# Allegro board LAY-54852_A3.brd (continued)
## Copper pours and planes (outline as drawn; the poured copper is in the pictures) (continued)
LPD4X_VDDQ_0V6 on TOP: 68.64,42.84 69.79,42.84 70.11,42.51 70.11,36.3 69.76,35.95 68.38,35.95 68.38,38.37 68.04,38.71 68.04,41.11 68.55,41.63 68.55,42.76
NVCC_SD2 on L3_PWR: 90.3,50.98 90.48,50.98 90.72,50.74 91.91,50.74 92.31,50.34 92.31,38.89 86.16,32.73 72.27,32.73 67.67,37.34 60.42,37.34 59.97,37.79 59.97,39.35 60.11,39.5 72.18,39.5 73.12,38.55 73.12,35.73 73.79,35.07 84.5,35.07 90.83,41.4 90.83,49.69 90.24,50.27 90.24,50.92
PD_USB_VBUS_IN on TOP: 46.66,24.37 46.96,24.37 46.97,24.38 47.06,24.29 47.06,21.86 46.28,21.07 45.42,21.07 45.25,21.24 45.25,24.6 45.41,24.76 46.27,24.76
USB1_VBUS_IN on TOP: 23.62,19.36 25,19.36 25.59,18.77 25.59,16.48 25.61,16.47 25.53,16.39 25.06,16.39 24.64,15.98 24.64,15.38 23.58,14.31 23.19,14.31 23.1,14.23 23.1,13.59 23.38,13.31 23.89,13.31 24.11,13.08 24.11,12.62 23.92,12.43 22.03,12.43 21.53,12.93 21.53,14.52 22.09,15.09 23.16,15.09 23.46,15.38 23.46,19.2
USB_PD_VBUS_F on TOP: 38.48,13.67 40.33,13.67 40.48,13.52 40.48,8.86 39.76,8.14 36.12,8.14 35.48,8.78 35.48,11.79 36.33,12.64 37.45,12.64
USB_PD_VBUS_F on TOP: 47.65,24.98 47.65,23.14 47.54,23.04 47.4,23.04 47.28,23.16 47.28,24.31 47.03,24.56 46.86,24.56 46.62,24.8 46.62,26.77 46.76,26.9 48.27,26.9 48.67,26.51 48.67,25.6 48.38,25.31 47.98,25.31
USB_PD_VBUS_F on L3_PWR: 45.79,26.46 47.32,26.46 47.71,26.07 47.71,12.66 46.41,11.36 36.93,11.36 36.69,11.6 36.69,14.18 36.88,14.37 43.08,14.37 45.2,16.49 45.2,25.87
USBC_VBUS on TOP: 25.39,10.72 26.69,10.72 26.96,10.45 26.96,9.07 28.4,7.63 28.4,6.49 28.53,6.35 28.53,5.83 28.4,5.7 27.97,5.7 27.88,5.79 27.88,6.43 27.98,6.53 27.98,7.47 27.55,7.91 26.22,7.91 25.36,8.77 25.36,10.68
USBC_VBUS_F on TOP: 22.02,11.94 23.9,11.94 24.12,11.72 24.12,8.7 23.86,8.44 22.07,8.44 21.74,8.77 21.74,11.66
USBC_VBUS_F on TOP: 25.28,22.45 27.97,22.45 28.16,22.26 28.16,20.33 26.4,18.56 26.4,16.89 26.57,16.72 27.14,16.72 27.23,16.63 27.23,16.52 27.14,16.44 25.85,16.44 25.78,16.5 25.78,19.01 25.06,19.73 25.06,22.24
USBC_VBUS_F on BOTTOM: 23.37,20.05 27.07,20.05 27.56,19.55 27.56,17.82 27.09,17.36 24.77,17.36 24.26,16.84 24.26,11.04 23.84,10.62 22.23,10.62 21.52,11.34 21.52,18.2
VCAN_5V on TOP: 40.08,81.4 42.61,81.4 43.04,80.97 43.04,77.88 43.42,77.49 43.42,77.06 43.18,76.83 40.14,76.83 39.61,77.36 39.61,80.92
VMIC_1V8 on TOP: 13.25,77.41 15.53,77.41 16.14,76.8 16.14,76.03 15.3,75.19 15.3,73.62 14.98,73.3 14.07,73.3 12.89,74.48 12.89,76.62 13.09,76.82 13.09,77.25
VPCIE_3V3 on TOP: 113.88,14.99 115.6,14.99 115.75,14.84 115.75,10.09 114.92,9.26 113.37,9.26 112.44,8.32 112.44,7.84 112.24,7.64 109.91,7.64 109.61,7.94 109.61,11.23 110.44,12.06 112.49,12.06 113.3,12.87 113.3,14.41
VPCIE_3V3 on TOP: 132.4,14.88 136.07,14.88 136.53,14.43 136.53,12.38 136.85,12.06 136.85,9.55 137,9.39 133.31,9.39 132.4,10.3
VPCIE_3V3 on TOP: 132.26,36.46 133.38,36.46 133.7,36.78 135.86,36.78 135.97,36.88 137.24,36.88 137.41,36.7 137.41,35.61 136.93,35.13 135.91,35.13 135.74,35.3 133.11,35.3 132.7,34.89 132.7,33.79 132.67,33.77 132.4,33.77 132.33,33.83 132.33,35.21 132,35.55 132,36.2
VPCIE_3V3 on BOTTOM: 128.96,36.47 134.05,36.47 134.26,36.67 135.75,36.67 136.14,36.28 136.14,35.46 135.59,34.9 132.94,34.9 132.64,34.6 132.64,32.21 130.91,30.48 130.91,25.43 131.83,24.51 132.18,24.51 134.8,21.9 136.02,20.67 136.02,13.12 135.59,12.69 118.25,12.69 113.1,7.54 109.58,7.54 108.87,8.24 108.87,13.7 111.79,16.62 119.43,16.62 121.57,18.76 128.95,18.76 129.55,19.37 129.55,20.68 128.09,22.15 128.09,35.6
VRPI_3V3 on TOP: 86.68,78.79 87.63,78.79 89.08,77.34 89.08,74.71 88.79,74.41 87.54,74.41 87.3,74.65 84.75,74.65 84.2,75.2 84.2,77.09 84.38,77.27 85.75,77.27 86.17,77.69 86.17,78.29
VRPI_5V on TOP: 84.54,83.37 91.32,83.37 91.46,83.24 91.46,79.52 91.26,79.32 86.45,79.32 85.95,79.83 85.95,81.08 85.27,81.77 84.33,81.77 84.2,81.89 84.2,83.03
VSYS_5V on TOP: 69.88,30.45 69.88,29.56 69.74,29.42 68.03,29.42 68,29.46 68,30.39 68.12,30.51 69.82,30.51
VSYS_5V on TOP: 65.21,35.33 66.1,35.33 66.24,35.19 66.24,33.48 66.2,33.44 65.27,33.44 65.15,33.57 65.15,35.27
VSYS_5V on TOP: 36.37,45.09 42.79,45.09 45.56,42.32 48.87,42.32 49.3,41.89 51.15,41.89 51.32,41.72 51.32,41.12 52.35,41.12 52.53,40.93 52.58,40.97 53.94,40.97 54.55,41.58 54.55,42.87 55.22,43.54 58.49,43.54 59.28,42.74 59.28,41.05 58.51,40.27 57.61,40.27 57.04,39.7 57.04,38.16 56.74,37.85 53.91,37.85 53.18,38.57 49.08,38.57 47.79,39.87 44.22,39.87 42.59,41.5 38.71,41.5 36.98,43.23 36.28,43.23 35.99,43.52 35.99,44.71
VSYS_5V on TOP: 132.38,33.47 132.63,33.47 132.76,33.34 132.76,31.81 132.91,31.65 136.73,31.65 136.98,31.4 136.98,28.9 136.7,28.61 134.91,28.61 134.65,28.87 134.65,29.84 134.16,30.34 133.21,30.34 132.35,31.2 132.35,33.44
VSYS_5V on TOP: 28.68,22.23 32.89,22.23 33.06,22.07 33.06,21.44 32.25,20.64 32.25,20.13 32.05,19.93 29.85,19.93 28.35,18.43 27.39,18.43 27.18,18.22 27.18,16.89 27.11,16.81 26.71,16.81 26.5,17.02 26.5,18.39 28.44,20.33 28.44,21.99
VSYS_5V on TOP: 63.79,25.86 62.9,25.86 62.76,26 62.76,27.71 62.8,27.74 63.73,27.74 63.85,27.62 63.85,25.92
VSYS_5V on BOTTOM: 136.9,27.24 135.4,27.24 135.08,27.56 135.08,31.06 135.2,31.19 137.19,31.19 137.57,30.81 137.57,27.91
VSYS_5V on BOTTOM: 63.52,35.55 69.88,35.55 70.36,35.07 70.36,27.39 70.42,27.32 70.42,25.75 69.33,24.66 68.81,24.66 68.74,24.58 61.75,24.58 60.8,25.53 60.8,26.73 60.98,26.91 61.88,26.91 62.11,27.14 62.11,27.66 62.16,27.72 64.44,27.72 64.55,27.61 64.55,27.09 64.54,27.07 64.54,26.75 65.25,26.03 66.14,26.03 68.05,27.94 68.05,33.23 67.74,33.54 58.14,33.54 56.38,35.31 56.38,41.2 56.57,41.39 58.35,41.39 58.52,41.22 58.52,38.8 58.96,38.37 60.7,38.37
VSYS_5V on BOTTOM: 107.01,4 109.83,4 110.11,3.72 110.11,1.87 109.96,1.72 107.22,1.72 106.84,2.1 106.84,3.84
VSYS_5V on BOTTOM: 39.5,43.63 39.5,40.72 36.65,37.87 33.84,37.87 30.91,34.95 30.91,25.75 32.55,24.11 32.55,20.35 32.01,19.82 29.43,19.82 27.3,21.95 27.3,36.73 32.85,42.28 32.85,43.75 33.45,44.36 38.78,44.36
VSYS_5V on L3_PWR: 29.92,22.11 32.2,22.11 32.48,21.84 32.48,20.33 32.45,20.31 32.45,16.08 33,15.53 35.89,15.53 36.32,15.1 36.32,11.51 36.93,10.91 48.26,10.91 50.15,9.02 109.58,9.02 111.56,7.04 111.56,2.37 110.76,1.57 106.81,1.57 106.2,0.96 49.72,0.96 49.52,1.16 49.52,4.71 48.51,5.71 38.78,5.71 36.16,8.34 32.91,8.34 32.05,9.2 32.05,12.46 29.54,14.97 29.54,21.74 ; 1 cut-out
N111686466 on TOP: 35.71,42.16 36.78,42.16 38.89,40.05 42.95,40.05 43.52,39.49 43.52,37.85 42.87,37.2 41.2,37.2 39.72,35.72 39.72,34.32 39.56,34.16 39.41,34.16 39.3,34.26 39.3,34.96 39.32,34.97 39.32,37.01 36.97,39.35 36.97,41.13 36.51,41.59 35.59,41.59 35.46,41.73 35.46,41.9
N111686641 on TOP: 49.06,8.53 59.07,8.53 59.82,7.78 59.82,6.63 59.52,6.33 57.02,6.33 56.07,7.28 49.05,7.28 48.84,7.49 48.84,8.31
N113526638 on TOP: 66.33,38.02 67.6,38.02 67.66,37.96 67.66,35.72 67.01,35.08 67.01,33.52 66.93,33.43 66.48,33.43 66.34,33.57 66.34,38.01
N113526990 on TOP: 70.23,33.28 71.54,33.28 71.69,33.12 71.69,30.86 71.49,30.66 68.04,30.66 67.99,30.71 67.99,31.13 68.15,31.29 69.45,31.29 70.11,31.95 70.11,33.16
N113527183 on TOP: 72.3,29.69 73.83,29.69 74.41,29.11 75.47,29.11 75.61,28.97 75.61,25.21 75.53,25.14 73.83,25.14 72.76,26.2 72.26,26.2 72.22,26.25 72.22,29.61
N113527270 on TOP: 68.08,29.29 69.79,29.29 70.2,29.7 71.5,29.7 71.65,29.55 71.65,27.54 71.43,27.33 70.4,27.33 70.22,27.51 70.22,28.13 69.73,28.62 68.08,28.62 67.99,28.71 67.99,29.2
N113527504 on TOP: 64.57,27.68 64.65,27.6 64.65,25.37 64.75,25.27 64.75,22.88 64.63,22.76 63.54,22.76 63.39,22.91 63.39,25.18 63.96,25.76 63.96,27.56 64.08,27.68
N113527663 on TOP: 62.62,27.57 62.65,27.54 62.65,23.21 62.44,22.99 61.55,22.99 61.44,23.1 61.44,25.22 62.17,25.96 62.17,27.48 62.26,27.57
N113527832 on TOP: 64.19,37.97 65.07,37.97 65.21,37.83 65.21,35.77 65.02,35.58 65.02,33.54 64.98,33.5 64.45,33.5 64.39,33.56 64.39,35.84 64.1,36.14 64.1,37.88
N115751791 on TOP: 132.96,34.75 134.85,34.75 134.94,34.65 134.94,34.08 133.5,34.08 133.3,33.88 133.3,31.98 133.15,31.84 132.98,31.84 132.89,31.93 132.89,34.67
N115751791 on BOTTOM: 133.22,34.65 135.89,34.65 136.37,34.16 136.37,32.97 135.99,32.59 133.45,32.59 133.05,32.99 133.05,34.47
N115938225 on BOTTOM: 105.81,26.81 107.22,26.81 107.45,26.57 107.45,26.14 107.68,25.91 108.62,25.91 109.01,25.53 109.01,24.67 108.71,24.37 107.28,24.37 107.1,24.55 105.04,24.55 104.89,24.7 104.89,25.6 105.18,25.89 105.18,26.18
N115938505 on BOTTOM: 102.01,30.55 106.29,30.55 106.78,30.06 106.78,28.81 106,28.02 104.52,28.02 104.28,28.26 103.36,28.26 102.86,27.77 102.86,24.1 102.12,23.36 98,23.36 97.41,23.95 97.41,25.95

Small or netless copper shapes (teardrops, artwork), in the pictures only: 2 on TOP

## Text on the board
BOTTOM: 170-54852 REV A3
Ref Des/Silkscreen Bottom: 700-54852 REV X | SCH-54852 REV X | S/N
User.Comments: 22. THIS FAB_VIAFILL.ART SHOWS LOCATIONS OF VIA-IN-PAD TO BE FILLED.
Ref Des/Silkscreen Top: SW601[1:4] | 1100 | 0100 | FLEXSPI | 1011 | 0011 | MICROSD | EMMC | 1010 | 0010 | 1001 | DOWNLOAD | 0001 | CORTEX-M | CORTEX-A | GND | 5V | H | L | T0/1 | 1V8 | 3V3 | SCL | SDA | STBY | WDOG | FSUS | PWR | RC | FSL | LC | A | U | 1 | 17 | ON/OFF | RST | BMODE | CAN | PD | ADC | TAMPER | LPDDR4 | I2C CN | SW | M.2 | E | MicroSD | EXP CN | DBG | USB | ENET | AUD | IMU | MCIMX93-QSB A3
DIMENSION: GRID ORIGIN | PRIMARY DATUM | CANNOT ADD ANY PLANE ON EVERY LAYER ON THIS BOARD | 23.  ANTENNA BOARD CANNOT BE SEPERATED WITH THE MAIN BOARD.USE V-CUT FOR THE CONNECTION. | V-CUT DETAILS:   SEE DETAIL 'E' | CORE | 3.49 | 3.97 | 0.02 | THIS BOARD WAS DESIGNED FOR MAXIMUM FLEXIBILITY IN SOFTWARE DEVELOPMENT AND DEMONSTRATES | PRELIMINARY -SUBJECT TO CHANGE | NXP CONFIDENTIAL AND PROPRIETARY | MULTIPLE FUNCTIONS POSSIBLE WITH I.MX PROCESSORS. ALTHOUGH BEST DESIGN PRACTICES HAVE | BEEN APPLIED,SOME AREAS MAY NOT BE SUITABLE FOR A MASS-PRODUCTION DESIGN | 19 | 16 | 22 | ONLY ON BOTTOM SIDE 2x | 1/3 PCB THICKNESS | BREAKING EDGE | DETAIL-E | TOP SIDE | BOT SIDE | V-CUT(DO NOT SPLIT) | 23 | DETAIL A
User.10: ALL PARTS, MATERIALS AND FINISHED | ASSEMBLY SHALL NOT CONTAIN ANY OF | THE SUBSTANCES OF VERY HIGH CONCERN | (SVHC) ABOVE THE THRESHOLD VALUE PER | THE CURRENT ECHA LIST OF SVHC'S AND | WITH ANNEX XIV AND ANNEX XVII OF REACH | DIRECTIVE 76/769/EEC. A CERTIFICATE OF | COMPLIANCE IS REQUIRED UPON REQUEST. | ASSEMBLY SHALL MEET THE RoHS | COMMISSION DELEGATED DIRECTIVE (EU) | 2015/863 OF 31 MARCH  2015 AMENDING | ANNEX II TO DIRECTIVE 2011/65/EU. A | CERTIFICATE OF COMPLIANCE IS | REQUIRED UPON REQUEST. | CHANGED THICKNESS TO 1.6MM,ADDED RTC | CHANGED U908,J1101,J1708. ADDED U1714,U58 | REMOVE TP1906,ADD TP920,D302 | 12-19-22 | 14-07-23 | 17-11-23 | F.X | A1 | A2 | A3 | NONE | 1
User.11: L4_BOTTOM | L1_TOP | 3.6 | 50 | 3.7 | 4 | 85 | 4.5 | 3.2 | 6
User.37: FIGURE | FINISHED_SIZE | 8.0 | 10.1 | 16.0 | 18.0 | 28.0 | 32.0 | 35.0 | 40.0 | 55.0 | 63.0 | 80.0 | 166.0 | 26.0 | 33.4 | 37.4 | 39.0 | 43.0 | 59.0 | 67.0 | 68.0 | 128.0 | 44.0x20.0 | 47.0x20.0 | 51.0x20.0 | 59.0x20.0 | ROTATION | - | 90.000 | DRILL CHART: TOP to BOTTOM | ALL UNITS ARE IN MILS | TOLERANCE_DRILL | +0.0/-0.0 | +0.0/-8.0 | +0.0/-10.0 | +2.0/-2.0 | +4.0/-0.0 | +3.0/-3.0 | +1.0/-2.0 | +1.0/-1.0 | +4.0/-4.0 | PLATED | NON-PLATED | QTY | 184 | 1657 | 53 | 24 | 3 | 6 | 4 | 18 | 2 | 1 | 2000 | TOTAL HOLES:
